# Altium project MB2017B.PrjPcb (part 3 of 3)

## Sheet Sensors_2.SchDoc: Sensors 2
size A4; Date: Not used; ApprovedBy: Not used; CheckedBy: Not used; Author: Not used; CompanyName: STMicroelectronics; DrawnBy: Not used; Engineer: Not used; Organization: Not used; Address1: Not used; Address2: Not used; Address3: Not used; Address4: Not used; DocumentNumber: Not used; Revision: Not used; SheetNumber: 6; SheetTotal: 7
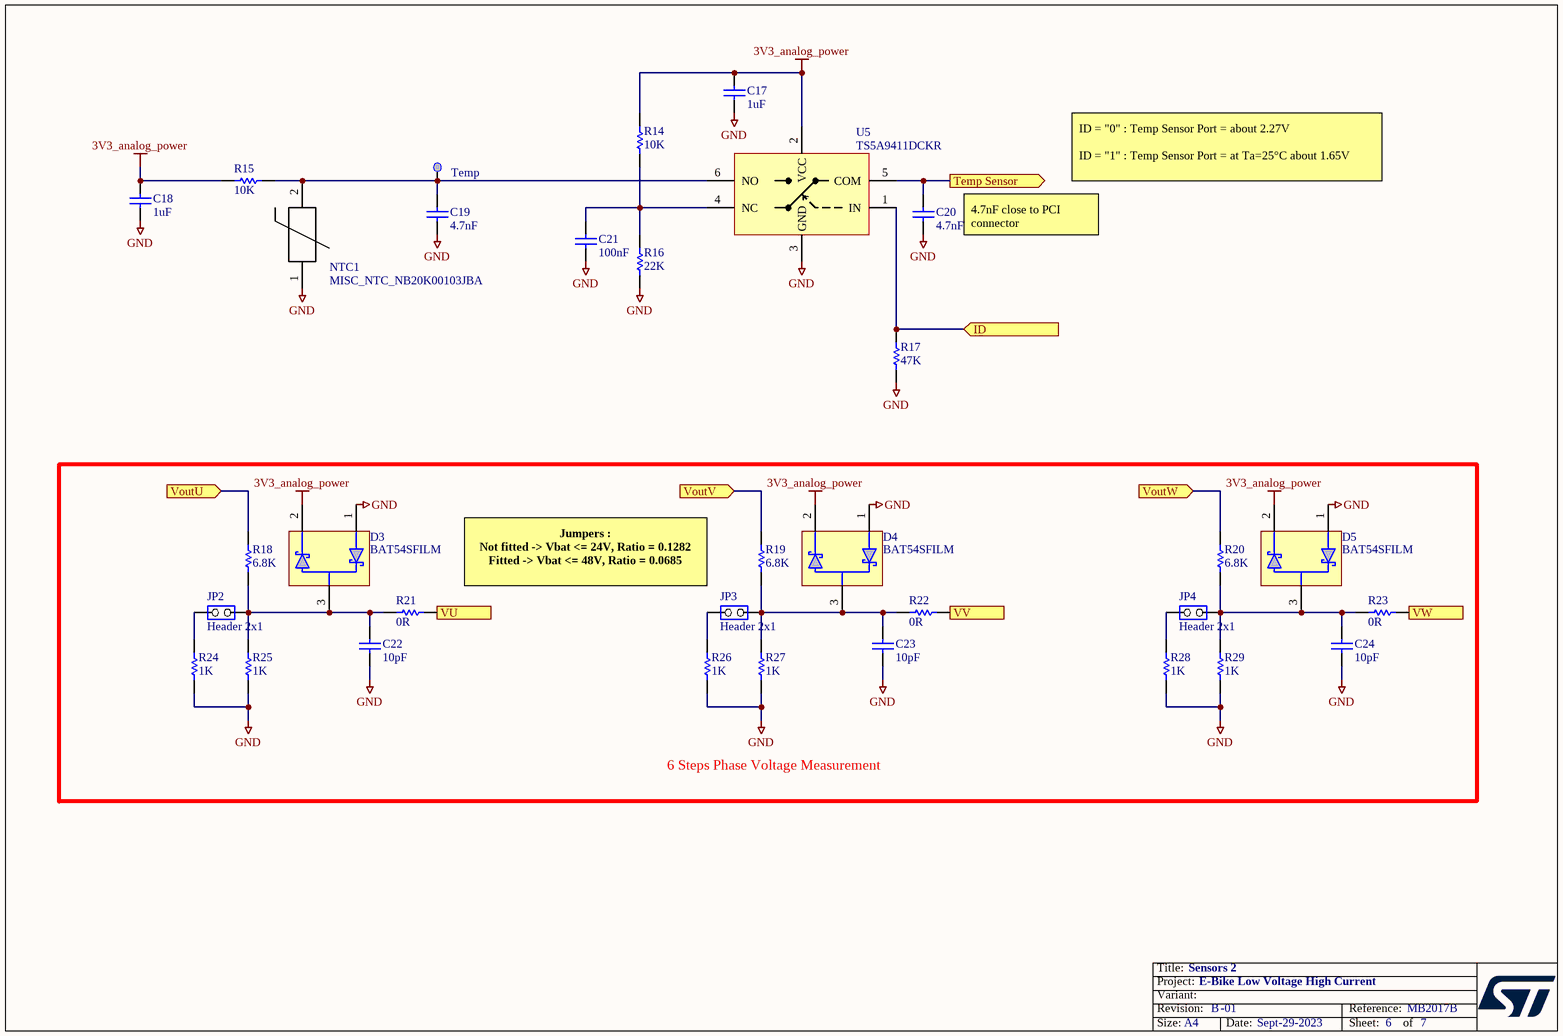
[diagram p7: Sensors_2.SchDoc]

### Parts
C17  value 1uF  [C0805_H0P85]  (hidden comment: Capacitor)
C18  value 1uF  [C0805_H0P85]  (hidden comment: Capacitor)
C19  value 4.7nF  [C0603]  (hidden comment: Capacitor)
C20  value 4.7nF  [C0603]  (hidden comment: Capacitor)
C21  value 100nF  [C0603]  (hidden comment: Capacitor)
C22  value 10pF  [C0603]  (hidden comment: Capacitor)
C23  value 10pF  [C0603]  (hidden comment: Capacitor)
C24  value 10pF  [C0603]  (hidden comment: Capacitor)
D3  value BAT54SFILM  [DIO_SOT23]  (hidden comment: DIODE_3P_DUAL_SERIES)
D4  value BAT54SFILM  [DIO_SOT23]  (hidden comment: DIODE_3P_DUAL_SERIES)
D5  value BAT54SFILM  [DIO_SOT23]  (hidden comment: DIODE_3P_DUAL_SERIES)
JP2  value Header 2x1  [CON_SAMTEC_TSW-102-07-G-S]  (hidden comment: Jumper_Header 2x1)
JP3  value Header 2x1  [CON_SAMTEC_TSW-102-07-G-S]  (hidden comment: Jumper_Header 2x1)
JP4  value Header 2x1  [CON_SAMTEC_TSW-102-07-G-S]  (hidden comment: Jumper_Header 2x1)
NTC1  MISC_NTC_NB20K00103JBA  [NTC1206_AVX_NB20_H1P5]
R14  value 10K  [R0603]  (hidden comment: Resistor)
R15  value 10K  [R0603]  (hidden comment: Resistor)
R16  value 22K  [R0603]  (hidden comment: Resistor)
R17  value 47K  [R0603]  (hidden comment: Resistor)
R18  value 6.8K  [R0805_H0P5]  (hidden comment: Resistor)
R19  value 6.8K  [R0805_H0P5]  (hidden comment: Resistor)
R20  value 6.8K  [R0805_H0P5]  (hidden comment: Resistor)
R21  value 0R  [R0805]  (hidden comment: Resistor)
R22  value 0R  [R0805]  (hidden comment: Resistor)
R23  value 0R  [R0805]  (hidden comment: Resistor)
R24  value 1K  [R0603]  (hidden comment: Resistor)
R25  value 1K  [R0603]  (hidden comment: Resistor)
R26  value 1K  [R0603]  (hidden comment: Resistor)
R27  value 1K  [R0603]  (hidden comment: Resistor)
R28  value 1K  [R0603]  (hidden comment: Resistor)
R29  value 1K  [R0603]  (hidden comment: Resistor)
Temp  Test Point  [TP_SMD_1MM]  (value not drawn)  (no BOM)
U5  value TS5A9411DCKR  [ICC_SC70-6_DCK_R-PDSO-G6_2X1P25_P065]  (hidden comment: IC_TS5A9411DCKR)

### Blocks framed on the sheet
6 Steps Phase Voltage Measurement: C22-C24 D3-D5 JP2-JP4 R18-R29

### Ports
ID (in), Temp Sensor (out), VoutU (in), VoutV (in), VoutW (in), VU (out), VV (out), VW (out)

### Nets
3V3_analog_power: C17.2 C18.2 D3.2 D4.2 D5.2 R14.2 R15.1 U5.2(VCC)
GND: C17.1 C18.1 C19.1 C20.1 C21.1 C22.1 C23.1 C24.1 D3.1 D4.1 D5.1 NTC1.1 R16.1 R17.1 R24.1 R25.1 R26.1 R27.1 R28.1 R29.1 U5.3(GND)
ID: R17.2 U5.1(IN) ; port ID
Temp Sensor: C20.2 U5.5(COM) ; port Temp Sensor
VoutU: R18.2 ; port VoutU
VoutV: R19.2 ; port VoutV
VoutW: R20.2 ; port VoutW
VU: R21.1 ; port VU
VV: R22.1 ; port VV
VW: R23.1 ; port VW
NetC19_2: C19.2 NTC1.2 R15.2 Temp.1 U5.6(NO)
NetC21_2: C21.2 R14.1 R16.2 U5.4(NC)
NetC22_2: C22.2 D3.3 JP2.2(NO) R18.1 R21.2 R25.2
NetC23_2: C23.2 D4.3 JP3.2(NO) R19.1 R22.2 R27.2
NetC24_2: C24.2 D5.3 JP4.2(NO) R20.1 R23.2 R29.2
NetJP2_1: JP2.1(COMMON) R24.2
NetJP3_1: JP3.1(COMMON) R26.2
NetJP4_1: JP4.1(COMMON) R28.2

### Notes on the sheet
- ID = "0" : Temp Sensor Port = about 2.27V
  ID = "1" : Temp Sensor Port = at Ta=25°C about 1.65V
- (near C20) 4.7nF close to PCI connector
- Jumpers :
  Not fitted -> Vbat <= 24V, Ratio = 0.1282
  Fitted -> Vbat <= 48V, Ratio = 0.0685

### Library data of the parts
C17 C18 = MCD-01550: Capacitor, MLCC, 1uF, 16V, X5R, +/-10%, 0805, T=0.85mm; Part_Preference: Recommended; Manufacturer: YAGEO; Manufacturer_Part_Number: CC0805KRX5R7BB105; Component_Country_Of_Origin: China; ShowFields: YES; ID: 3650
C19 C20 = MCD-01049: Capacitor, MLCC, 4.7nF, 100V, X7R, +/-10%, 0603, T=1mm; Part_Preference: Recommended; Manufacturer: AVX; Manufacturer_Part_Number: 06031C472K4T2A; Component_Country_Of_Origin: El Salvador; ShowFields: YES; ID: 2975
C21 = MCD-01099: Capacitor, MLCC, 100nF, 50V, X7R, +/-10%, 0603, T=0.8mm; BMS_Part_Number: 9142278; Part_Preference: Recommended; Manufacturer: YAGEO; Manufacturer_Part_Number: CC0603KRX7R9BB104; Order_Code_RS: 669-8767; Component_Country_Of_Origin: China; ShowFields: YES; ID: 3397
C22-C24 = MCD-00637: Capacitor, MLCC, 10pF, 50V, NPO, +/-5%, 0603, T=0.8mm; Part_Preference: Recommended; Manufacturer: YAGEO; Manufacturer_Part_Number: CC0603JRNPO9BN100; Order_Code_RS: 616-9054; Component_Country_Of_Origin: China; ShowFields: YES; ID: 3104
D3-D5 = MCD-03277: Diode, Schottky, 0V3, 300mA, 40V, SOT-23; Part_Preference: Recommended; Manufacturer: STMICROELECTRONICS; Order_Code_RS: 714-6863; Component_Country_Of_Origin: China; ShowFields: YES; ID: 5393
JP2-JP4 = MCD-00045: Header, 2x1, 2.54mm, VR, TH, T=5.84mm/2.54mm; Part_Type: Connector; Part_Preference: Recommended; Manufacturer: SAMTEC; Manufacturer_Part_Number: TSW-102-07-G-S; Full_Alternate_Internal_Part_Number: MCD-02390; Partial_Alternate_Internal_Part_Number: MCD-02957, MCD-03720; Order_Code_RS: 2505044; Component_Country_Of_Origin: China, Costa Rica, Malaysia, USA, Vietnam; ShowFields: YES; ID: 2545
NTC1 = MCD-03782: NTC SMD Thermistor, 10k, 1206, +/-5%, 0.24W; Part_Type: Resistor; Part_Preference: Not recommended; Manufacturer: AVX; Order_code_RS: 697-4673; Component_Country_Of_Origin: France°; ShowFields: YES; ID: 5898
R14 R15 = MCD-00220: Resistor, 10K, 0603, +/-1%, 1/10W; Part_Preference: Recommended; Manufacturer: YAGEO; Manufacturer_Part_Number: RC0603FR-0710KL; Component_Country_Of_Origin: China; ShowFields: YES; ID: 2649
R16 = MCD-00430: Resistor, 22K, 0603, +/-1%, 1/10W; Part_Preference: Recommended; Manufacturer: YAGEO; Manufacturer_Part_Number: RC0603FR-0722KL; Component_Country_Of_Origin: China; ShowFields: YES; ID: 2847
R17 = MCD-00222: Resistor, 47K, 0603, 1%, 1/10W; Part_Preference: Recommended; Manufacturer: YAGEO; Manufacturer_Part_Number: RC0603FR-0747KL; Component_Country_Of_Origin: China; ShowFields: YES; ID: 2645
R18-R20 = MCD-01562: Resistor, 6K8, 0805, +/-0.1%, 1/8W, +/-50ppm/°C; Part_Preference: Recommended; Manufacturer: YAGEO; Manufacturer_Part_Number: RT0805BRE076K8L; Component_Country_Of_Origin: Taiwan; ShowFields: YES; ID: 3662
R21-R23 = MCD-00179: Resistor, 0R, 0805, +/-5%, 1/8W; Part_Preference: Recommended; Manufacturer: YAGEO; Manufacturer_Part_Number: RC0805JR-070RL; Component_Country_Of_Origin: China; ShowFields: YES; ID: 2685
R24-R29 = MCD-00070: Resistor, 1K, 0603, +/-1%, 1/10W; Part_Preference: Recommended; Manufacturer: YAGEO; Manufacturer_Part_Number: RC0603FR-071KL; Order_Code_RS: 9238484RL; Component_Country_Of_Origin: China; ShowFields: YES; ID: 2522
Temp = MCD-00074: Test Point 1mm; Part_Type: Misc; Part_Preference: Recommended; ShowFields: YES; ID: 2518; Component_Country_Of_Origin: Unknown
U5 = MCD-04271: DC switch, 9R, Low Voltage, 1:2 SPDT analog switch; Part_Type: IC; Part_Preference: Recommended; Manufacturer: TEXAS INSTRUMENTS; Order_Code_RS: 817-5600; ShowFields: YES; ID: 6387; Component_Country_Of_Origin: China, Malaysia, Thailand

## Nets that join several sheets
3V3_analog_power: Power_Supplies (6 pins), PCI_Connector (R54.2 R55.2 R57.1), Power_Stage (JP8.1 RV1.3), Sensors (30 pins), Sensors_2 (8 pins)
3V3_pci: Power_Supplies (C16.2 JP1.3), PCI_Connector (C26.1 CN1.A06)
+5V_power: Power_Supplies (7 pins), PCI_Connector (C25.1 CN1.A05 CN1.B05), Sensors (5 pins)
GND: Power_Supplies (35 pins), PCI_Connector (30 pins), Power_Stage (69 pins), Sensors (78 pins), Sensors_2 (21 pins)
Vbat: Power_Supplies (D1.2 R6.2 VBAT.1), Power_Stage (6 pins)
Vcc_Gate: Power_Supplies (6 pins), Power_Stage (12 pins)
Vcc_power: Power_Stage (20 pins), Sensors (R120.2 R143.2)
Vref_pci: PCI_Connector (C27.1 CN1.B06), Sensors (JP14.1)
Brake_Levers: PCI_Connector (R50.2), Sensors (Brake_Levers.1 C119.1 D19.3 R178.2)
En1: PCI_Connector (R36.2), Power_Stage (R82.1)
En2: PCI_Connector (R39.2), Power_Stage (R107.1)
En3: PCI_Connector (R42.2), Power_Stage (R103.1)
Hall H1: PCI_Connector (R43.2), Sensors (D14.1 H1.1 R140.1 R147.2)
Hall H2: PCI_Connector (R45.2), Sensors (D15.1 H2.1 R141.1 R148.2)
Hall H3: PCI_Connector (R46.1), Sensors (D17.1 H3.1 R142.1 R149.2)
HinU: PCI_Connector (R34.2 R53.1), Power_Stage (HinU.1 R68.2)
HinV: PCI_Connector (R37.2 R58.2), Power_Stage (HinV.1 R95.2)
HinW: PCI_Connector (R40.2 R56.2), Power_Stage (HinW.1 R104.2)
Icc_Current: PCI_Connector (R52.2), Sensors (C85.2 Icc_Current.1 R128.2)
Icc_Power+: Power_Stage (RPW.S1), Sensors (C82.2 U11.8)
Icc_Power-: Power_Stage (RPW.S2), Sensors (C82.1 U11.1)
ID: PCI_Connector (CN1.A08), Sensors_2 (R17.2 U5.1)
IoutU+: Power_Stage (IoutU+.1 JP5.1 RSU.S2), Sensors (R145.1 R152.1)
IoutU-: Power_Stage (RSU.S1), Sensors (R156.1 R159.2)
IoutV+: Power_Stage (IoutV+.1 JP7.1 RSV.S2), Sensors (R161.1 R165.1)
IoutV-: Power_Stage (RSV.S1), Sensors (R174.1 R181.2)
IoutW+: Power_Stage (IoutW+.1 JP6.1 RSW.S2), Sensors (R163.1 R166.1)
IoutW-: Power_Stage (RSW.S1), Sensors (R176.1 R182.2)
LinU: PCI_Connector (R35.1 R55.1), Power_Stage (LinU.1 R72.2)
LinV: PCI_Connector (R38.1 R54.1), Power_Stage (LinV.1 R99.2)
LinW: PCI_Connector (R41.1 R57.2), Power_Stage (LinW.1 R105.2)
Ocurrent1: PCI_Connector (R30.2), Power_Stage (R82.2 U7.2)
Ocurrent2: PCI_Connector (R31.2), Power_Stage (R107.2 U9.2)
Ocurrent3: PCI_Connector (R32.2), Power_Stage (R103.2 U8.2)
OV_Vcc_Power: PCI_Connector (R33.1), Sensors (OV_Vcc.1 R121.2)
Ref_Current_6S: PCI_Connector (R47.1), Sensors (JP14.3)
ShuntU+: PCI_Connector (CN1.A21), Sensors (C95.1 R145.2 R155.1 ShuntU+.1)
ShuntU-: PCI_Connector (CN1.B21), Sensors (C104.1 R159.1)
ShuntV+: PCI_Connector (CN1.A22), Sensors (C109.1 R161.2 R170.1 ShuntV+.1)
ShuntV-: PCI_Connector (CN1.B22), Sensors (C124.2 R181.1)
ShuntW+: PCI_Connector (CN1.A23), Sensors (C108.1 R163.2 R172.1 ShuntW+.1)
ShuntW-: PCI_Connector (CN1.B23), Sensors (C125.2 R182.1)
Temp Sensor: PCI_Connector (CN1.A28), Sensors_2 (C20.2 U5.5)
Throttle: PCI_Connector (R51.1), Sensors (C107.1 D18.3 R160.2 Throttle.1)
Vcc_Pw: PCI_Connector (R48.2), Sensors (C99.2 R144.2 Vcc_PW.1)
VoutU: Power_Stage (10 pins), Sensors (R115.2), Sensors_2 (R18.2)
VoutV: Power_Stage (10 pins), Sensors (R123.2), Sensors_2 (R19.2)
VoutW: Power_Stage (10 pins), Sensors (R133.2), Sensors_2 (R20.2)
VU: PCI_Connector (CN1.A25), Sensors (C74.2 R116.2 VU.1), Sensors_2 (R21.1)
VV: PCI_Connector (CN1.A26), Sensors (C81.2 R127.2 VV.1), Sensors_2 (R22.1)
VW: PCI_Connector (CN1.A27), Sensors (C87.2 R134.2 VW.1), Sensors_2 (R23.1)

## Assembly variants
Internal OPAMPS: not fitted GNDaux J2 J3 J5 J6 R21 R22 R23 R114 R122 R132 R152 R155 R156 R165 R166 R170 R172 R174 R176
External OPAMPS: not fitted C95 C104 C108 C109 C124 C125 GNDaux J2 J3 J5 J6 R21 R22 R23 R114 R122 R132 R145 R159 R161 R163 R181 R182
Single Shunt Internal Opamp: not fitted GNDaux J1 J4 R21 R22 R23 R114 R122 R132 R145 R155 R159 R163 R165 R170 R172 R174 R182
Single Shunt External Opamp: not fitted C95 C104 C108 C109 C124 C125 GNDaux J1 J4 R21 R22 R23 R114 R122 R132 R145 R155 R159 R161 R163 R172 R181 R182
6 Steps V1: not fitted C74 C81 C87 C109 C124 GNDaux J1 J4 R114 R116 R122 R127 R132 R134 R145 R155 R159 R163 R170 R172 R181 R182
6 Steps V2: not fitted C74 C81 C87 C109 C124 GNDaux J1 J4 R114 R116 R122 R127 R132 R134 R145 R155 R159 R161 R163 R172 R181 R182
